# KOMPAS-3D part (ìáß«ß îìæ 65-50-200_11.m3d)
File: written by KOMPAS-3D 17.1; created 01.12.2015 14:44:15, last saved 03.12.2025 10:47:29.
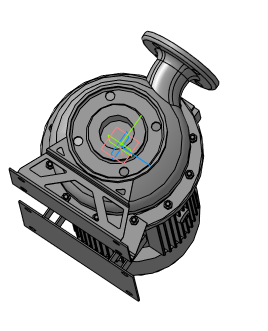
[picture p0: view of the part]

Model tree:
1. Операция без истории:3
